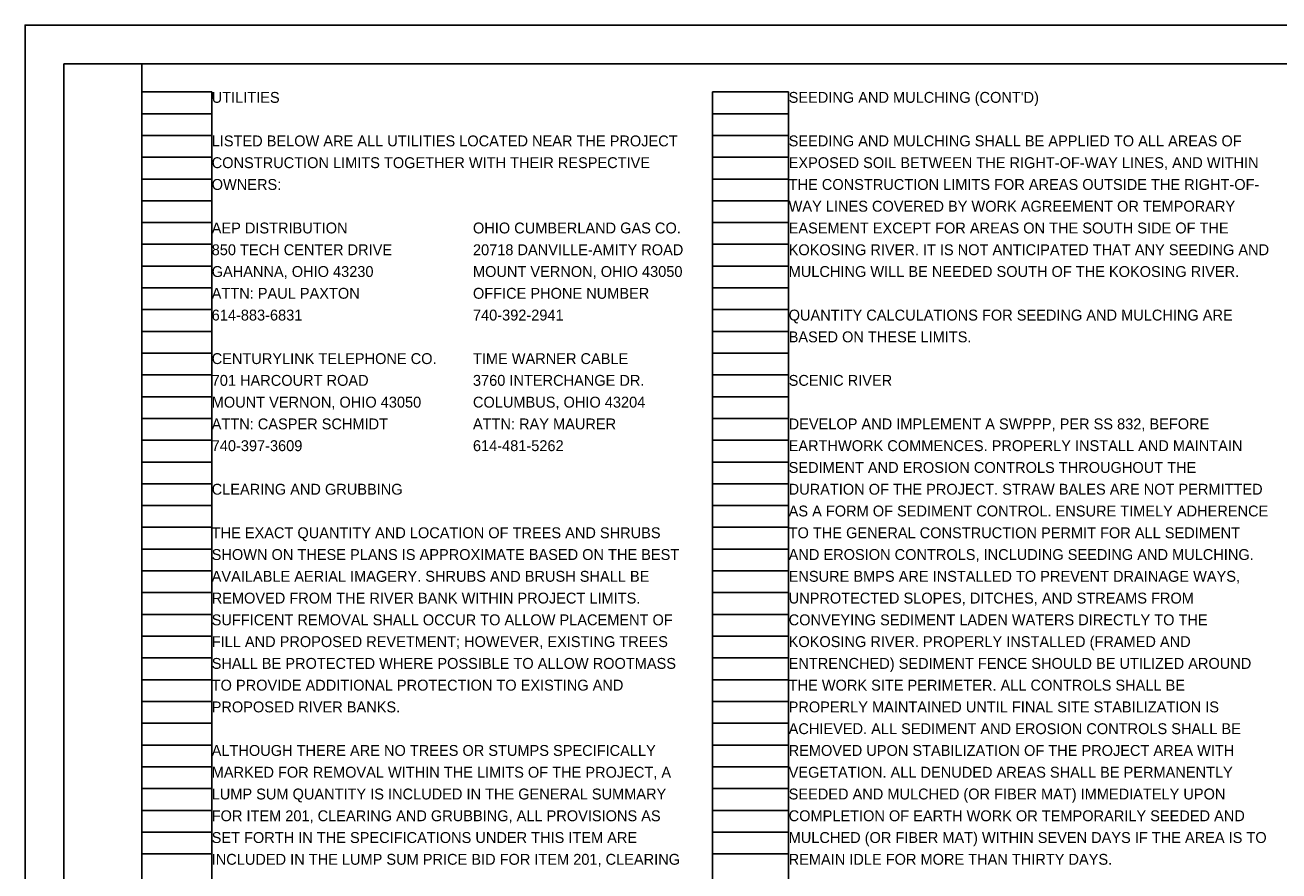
# Model space of a CAD drawing. Extents: x 0 to 58.9, y 0 to 22.
# Drawn here: x 0 to 16.12, y 11.12 to 22 of the extents above; entities that cross this region are included whole.
import ezdxf

# ---------------------------------------------------------------- set-up
doc = ezdxf.new("R2010")
doc.units = 0
for name, color, linetype in [('CS-ALGN-CNTR', 7, 'Continuous'), ('CS-ALGN-TEXT', 7, 'Continuous'), ('CS-ANNO-MATC', 7, 'Continuous'), ('CS-ANNO-MATC-MASK', 7, 'Continuous')]:
    doc.layers.add(name, color=color, linetype=linetype)

msp = doc.modelspace()

# ---------------------------------------------------------------- linework, layer by layer
at = {"layer": 'CS-ALGN-CNTR'}
msp.add_lwpolyline([(0, 0), (34, 0), (34, 22), (0, 22)], close=True, dxfattribs=at)
at = {"layer": 'CS-ALGN-TEXT'}
for points in [[(0.5, 21.5), (1.5, 21.5), (1.5, 0.5), (0.5, 0.5)], [(1.5, 21.5), (33.5, 21.5), (33.5, 0.5), (1.5, 0.5)]]:
    msp.add_lwpolyline(points, close=True, dxfattribs=at)
at = {"layer": 'CS-ANNO-MATC-MASK'}
for p, q in [((1.5, 0.98), (1.5, 21.14)), ((1.5, 21.14), (2.4, 21.14)), ((2.4, 0.98), (2.4, 21.14)), ((8.84, 0.98), (8.84, 21.14)), ((8.84, 21.14), (9.82, 21.14)), ((9.82, 0.98), (9.82, 21.14)), ((1.5, 20.86), (2.4, 20.86)), ((8.84, 20.86), (9.82, 20.86)), ((1.5, 20.58), (2.4, 20.58)), ((8.84, 20.58), (9.82, 20.58)), ((1.5, 20.3), (2.4, 20.3)), ((8.84, 20.3), (9.82, 20.3)), ((1.5, 20.02), (2.4, 20.02)), ((8.84, 20.02), (9.82, 20.02)), ((1.5, 19.74), (2.4, 19.74)), ((8.84, 19.74), (9.82, 19.74)), ((1.5, 19.46), (2.4, 19.46)), ((8.84, 19.46), (9.82, 19.46)), ((1.5, 19.18), (2.4, 19.18)), ((8.84, 19.18), (9.82, 19.18)), ((1.5, 18.9), (2.4, 18.9)), ((8.84, 18.9), (9.82, 18.9)), ((1.5, 18.62), (2.4, 18.62)), ((8.84, 18.62), (9.82, 18.62)), ((1.5, 18.34), (2.4, 18.34)), ((8.84, 18.34), (9.82, 18.34)), ((1.5, 18.06), (2.4, 18.06)), ((8.84, 18.06), (9.82, 18.06)), ((1.5, 17.78), (2.4, 17.78)), ((8.84, 17.78), (9.82, 17.78)), ((1.5, 17.5), (2.4, 17.5)), ((8.84, 17.5), (9.82, 17.5)), ((1.5, 17.22), (2.4, 17.22)), ((8.84, 17.22), (9.82, 17.22)), ((1.5, 16.94), (2.4, 16.94)), ((8.84, 16.94), (9.82, 16.94)), ((1.5, 16.66), (2.4, 16.66)), ((8.84, 16.66), (9.82, 16.66)), ((1.5, 16.38), (2.4, 16.38)), ((8.84, 16.38), (9.82, 16.38)), ((1.5, 16.1), (2.4, 16.1)), ((8.84, 16.1), (9.82, 16.1)), ((1.5, 15.82), (2.4, 15.82)), ((8.84, 15.82), (9.82, 15.82)), ((1.5, 15.54), (2.4, 15.54)), ((8.84, 15.54), (9.82, 15.54)), ((1.5, 15.26), (2.4, 15.26)), ((8.84, 15.26), (9.82, 15.26)), ((1.5, 14.98), (2.4, 14.98)), ((8.84, 14.98), (9.82, 14.98)), ((1.5, 14.7), (2.4, 14.7)), ((8.84, 14.7), (9.82, 14.7)), ((1.5, 14.42), (2.4, 14.42)), ((8.84, 14.42), (9.82, 14.42)), ((1.5, 14.14), (2.4, 14.14)), ((8.84, 14.14), (9.82, 14.14)), ((1.5, 13.86), (2.4, 13.86)), ((8.84, 13.86), (9.82, 13.86)), ((1.5, 13.58), (2.4, 13.58)), ((8.84, 13.58), (9.82, 13.58)), ((1.5, 13.3), (2.4, 13.3)), ((8.84, 13.3), (9.82, 13.3)), ((1.5, 13.02), (2.4, 13.02)), ((8.84, 13.02), (9.82, 13.02)), ((1.5, 12.74), (2.4, 12.74)), ((8.84, 12.74), (9.82, 12.74)), ((1.5, 12.46), (2.4, 12.46)), ((8.84, 12.46), (9.82, 12.46)), ((1.5, 12.18), (2.4, 12.18)), ((8.84, 12.18), (9.82, 12.18)), ((1.5, 11.9), (2.4, 11.9)), ((8.84, 11.9), (9.82, 11.9)), ((1.5, 11.62), (2.4, 11.62)), ((8.84, 11.62), (9.82, 11.62)), ((1.5, 11.34), (2.4, 11.34)), ((8.84, 11.34), (9.82, 11.34))]:
    msp.add_line(p, q, dxfattribs=at)

# ---------------------------------------------------------------- texts
at = {"layer": 'CS-ANNO-MATC'}
for s, p in [('UTILITIES ', (2.4, 21)), ("SEEDING AND MULCHING (CONT'D)", (9.82, 21)), ('LISTED BELOW ARE ALL UTILITIES LOCATED NEAR THE PROJECT ', (2.4, 20.44)), ('SEEDING AND MULCHING SHALL BE APPLIED TO ALL AREAS OF ', (9.82, 20.44)), ('CONSTRUCTION LIMITS TOGETHER WITH THEIR RESPECTIVE ', (2.4, 20.16)), ('EXPOSED SOIL BETWEEN THE RIGHT-OF-WAY LINES, AND WITHIN ', (9.82, 20.16)), ('OWNERS:  ', (2.4, 19.88)), ('THE CONSTRUCTION LIMITS FOR AREAS OUTSIDE THE RIGHT-OF-', (9.82, 19.88)), ('WAY LINES COVERED BY WORK AGREEMENT OR TEMPORARY ', (9.82, 19.6)), ('AEP DISTRIBUTION', (2.4, 19.32)), ('OHIO CUMBERLAND GAS CO. ', (5.76, 19.32)), ('EASEMENT EXCEPT FOR AREAS ON THE SOUTH SIDE OF THE ', (9.82, 19.32)), ('850 TECH CENTER DRIVE', (2.4, 19.04)), ('20718 DANVILLE-AMITY ROAD ', (5.76, 19.04)), ('KOKOSING RIVER. IT IS NOT ANTICIPATED THAT ANY SEEDING AND ', (9.82, 19.04)), ('GAHANNA, OHIO 43230', (2.4, 18.76)), ('MOUNT VERNON, OHIO 43050 ', (5.76, 18.76)), ('MULCHING WILL BE NEEDED SOUTH OF THE KOKOSING RIVER.', (9.82, 18.76)), ('ATTN: PAUL PAXTON', (2.4, 18.48)), ('OFFICE PHONE NUMBER ', (5.76, 18.48)), ('614-883-6831', (2.4, 18.2)), ('740-392-2941  ', (5.76, 18.2)), ('QUANTITY CALCULATIONS FOR SEEDING AND MULCHING ARE ', (9.82, 18.2)), ('BASED ON THESE LIMITS.', (9.82, 17.92)), ('CENTURYLINK TELEPHONE CO.', (2.4, 17.64)), ('TIME WARNER CABLE', (5.76, 17.64)), ('701 HARCOURT ROAD', (2.4, 17.36)), ('3760 INTERCHANGE DR. ', (5.76, 17.36)), ('SCENIC RIVER', (9.82, 17.36)), ('MOUNT VERNON, OHIO 43050', (2.4, 17.08)), ('COLUMBUS, OHIO 43204 ', (5.76, 17.08)), ('ATTN: CASPER SCHMIDT', (2.4, 16.8)), ('ATTN: RAY MAURER ', (5.76, 16.8)), ('DEVELOP AND IMPLEMENT A SWPPP, PER SS 832, BEFORE ', (9.82, 16.8)), ('740-397-3609', (2.4, 16.52)), ('614-481-5262', (5.76, 16.52)), ('EARTHWORK COMMENCES. PROPERLY INSTALL AND MAINTAIN ', (9.82, 16.52)), ('SEDIMENT AND EROSION CONTROLS THROUGHOUT THE ', (9.82, 16.24)), ('CLEARING AND GRUBBING', (2.4, 15.96)), ('DURATION OF THE PROJECT. STRAW BALES ARE NOT PERMITTED ', (9.82, 15.96)), ('AS A FORM OF SEDIMENT CONTROL. ENSURE TIMELY ADHERENCE ', (9.82, 15.68)), ('THE EXACT QUANTITY AND LOCATION OF TREES AND SHRUBS ', (2.4, 15.4)), ('TO THE GENERAL CONSTRUCTION PERMIT FOR ALL SEDIMENT ', (9.82, 15.4)), ('SHOWN ON THESE PLANS IS APPROXIMATE BASED ON THE BEST ', (2.4, 15.12)), ('AND EROSION CONTROLS, INCLUDING SEEDING AND MULCHING. ', (9.82, 15.12)), ('AVAILABLE AERIAL IMAGERY. SHRUBS AND BRUSH SHALL BE ', (2.4, 14.84)), ('ENSURE BMPS ARE INSTALLED TO PREVENT DRAINAGE WAYS, ', (9.82, 14.84)), ('REMOVED FROM THE RIVER BANK WITHIN PROJECT LIMITS. ', (2.4, 14.56)), ('UNPROTECTED SLOPES, DITCHES, AND STREAMS FROM ', (9.82, 14.56)), ('SUFFICENT REMOVAL SHALL OCCUR TO ALLOW PLACEMENT OF ', (2.4, 14.28)), ('CONVEYING SEDIMENT LADEN WATERS DIRECTLY TO THE ', (9.82, 14.28)), ('FILL AND PROPOSED REVETMENT; HOWEVER, EXISTING TREES ', (2.4, 14)), ('KOKOSING RIVER. PROPERLY INSTALLED (FRAMED AND ', (9.82, 14)), ('ENTRENCHED) SEDIMENT FENCE SHOULD BE UTILIZED AROUND ', (9.82, 13.72)), ('SHALL BE PROTECTED WHERE POSSIBLE TO ALLOW ROOTMASS ', (2.4, 13.72)), ('TO PROVIDE ADDITIONAL PROTECTION TO EXISTING AND ', (2.4, 13.44)), ('THE WORK SITE PERIMETER. ALL CONTROLS SHALL BE ', (9.82, 13.44)), ('PROPOSED RIVER BANKS.', (2.4, 13.16)), ('PROPERLY MAINTAINED UNTIL FINAL SITE STABILIZATION IS ', (9.82, 13.16)), ('ACHIEVED. ALL SEDIMENT AND EROSION CONTROLS SHALL BE ', (9.82, 12.88)), ('ALTHOUGH THERE ARE NO TREES OR STUMPS SPECIFICALLY ', (2.4, 12.6)), ('REMOVED UPON STABILIZATION OF THE PROJECT AREA WITH ', (9.82, 12.6)), ('MARKED FOR REMOVAL WITHIN THE LIMITS OF THE PROJECT, A ', (2.4, 12.32)), ('VEGETATION. ALL DENUDED AREAS SHALL BE PERMANENTLY ', (9.82, 12.32)), ('LUMP SUM QUANTITY IS INCLUDED IN THE GENERAL SUMMARY ', (2.4, 12.04)), ('SEEDED AND MULCHED (OR FIBER MAT) IMMEDIATELY UPON ', (9.82, 12.04)), ('FOR ITEM 201, CLEARING AND GRUBBING, ALL PROVISIONS AS ', (2.4, 11.76)), ('COMPLETION OF EARTH WORK OR TEMPORARILY SEEDED AND ', (9.82, 11.76)), ('SET FORTH IN THE SPECIFICATIONS UNDER THIS ITEM ARE ', (2.4, 11.48)), ('MULCHED (OR FIBER MAT) WITHIN SEVEN DAYS IF THE AREA IS TO ', (9.82, 11.48)), ('INCLUDED IN THE LUMP SUM PRICE BID FOR ITEM 201, CLEARING ', (2.4, 11.2)), ('REMAIN IDLE FOR MORE THAN THIRTY DAYS.', (9.82, 11.2))]:
    msp.add_text(s, height=0.14, dxfattribs=at).set_placement(p)

doc.saveas('drawing.dxf')
